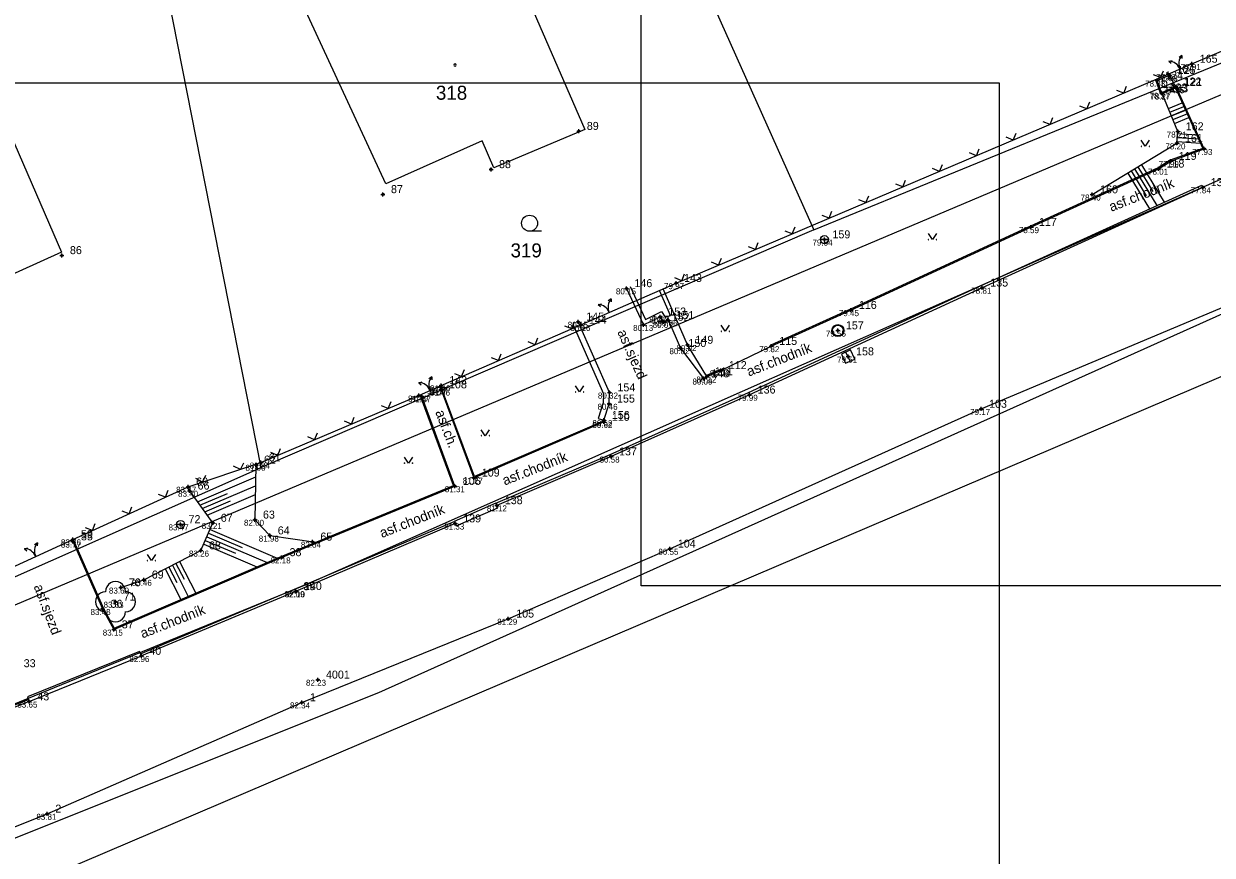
# Model space of a CAD drawing. Extents: x -454285 to -453563, y -1108687 to -1108249.
# Drawn here: x -454078.1 to -454018.7, y -1108543.4 to -1108501.8 of the extents above; entities that cross this region are included whole.
import ezdxf

# ---------------------------------------------------------------- set-up
doc = ezdxf.new("R2010")
doc.units = 0
for name, color, linetype in [('1', 7, 'Continuous'), ('14', 7, 'Continuous'), ('15', 7, 'Continuous'), ('2', 7, 'Continuous'), ('23', 7, 'Continuous'), ('25', 7, 'Continuous'), ('beton', 7, 'Continuous'), ('BODY_T1_2018', 7, 'Continuous'), ('CISLA_T1_2018', 7, 'Continuous'), ('obrubník', 7, 'Continuous'), ('okraj asf.komunikace', 7, 'Continuous'), ('oplocení', 7, 'Continuous'), ('rozhraní', 7, 'Continuous'), ('rámy', 7, 'Continuous'), ('sloup', 7, 'Continuous'), ('svahy', 7, 'Continuous'), ('svahy-hrana', 7, 'Continuous'), ('svahy-pata', 7, 'Continuous'), ('T', 7, 'Continuous'), ('uliční vpusť', 7, 'Continuous'), ('VYSKY_T1_2018', 7, 'Continuous'), ('zeleň', 7, 'Continuous'), ('šachtice', 7, 'Continuous')]:
    doc.layers.add(name, color=color, linetype=linetype)

# ---------------------------------------------------------------- blocks, each defined once
blk = doc.blocks.new('Z402')
for start, end in [(0, 180), (180, 0)]:
    blk.add_arc((0, 0), 0.15, start, end)
blk = doc.blocks.new('Z3040')
blk.add_line((1.5, 0), (0, 0))
blk.add_circle((0, 1), 1)
blk = doc.blocks.new('PLOT05')
for q in [(-0.265, 0.265), (0.265, 0.265)]:
    blk.add_line((0, 0), q)
blk = doc.blocks.new('BRANKA')
for p, q in [((-0.351, 0.589), (-0.179, 0.552)), ((-0.351, 0.589), (-0.284, 0.449)), ((0.361, 0.583), (0.188, 0.549)), ((0.361, 0.583), (0.291, 0.445))]:
    blk.add_line(p, q)
for centre, start, end in [((-0.618, 0.03), 357.17506, 64.46884), ((0.619, 0.02), 114.58945, 181.88322)]:
    blk.add_arc(centre, 0.619, start, end)
blk = doc.blocks.new('EL.SLOUP')
blk.add_line((0.4, 0), (-0.4, 0))
blk.add_line((0.4, 0), (-0.4, 0))
blk.add_lwpolyline([(0.4, 0), (-0.4, 0)])
blk.add_lwpolyline([(0.4, 0), (-0.4, 0)])
blk.add_circle((0, 0), 0.4)
blk.add_circle((0, 0), 0.4)
for start, end in [(270, 0), (270, 0), (180, 270), (180, 270)]:
    blk.add_arc((0, 0), 0.4, start, end)
blk = doc.blocks.new('šachtice_kruh_velká')
for radius in [0.5, 0.495, 0.495, 0.455, 0.455, 0.45]:
    blk.add_circle((0, 0), radius)
blk = doc.blocks.new('vpusť')
for p, q in [((0.25, 0.25), (-0.25, 0.25)), ((-0.25, 0.25), (-0.25, -0.25)), ((-0.25, 0), (0.25, 0)), ((0.25, -0.25), (0.25, 0.25)), ((-0.25, -0.25), (0.25, -0.25))]:
    blk.add_line(p, q)
blk = doc.blocks.new('strom')
blk.add_circle((0, 0), 0.1)
for centre, start, end in [((0, 1.02), 359.2723, 180.7277), ((-1.01, 0.01), 89.2723, 270.7277), ((1.01, 0.01), 269.2723, 90.7277), ((0, -1), 179.2723, 0.7277)]:
    blk.add_arc(centre, 0.998, start, end)
blk = doc.blocks.new('PARK')
for p, q in [((0, 0), (-1, 1.5)), ((1, 1.5), (0, 0))]:
    blk.add_line(p, q)
for centre, start, end in [((-1, 0), 0, 180), ((1, 0), 0, 180), ((1, 0), 180, 0), ((-1, 0), 180, 0)]:
    blk.add_arc(centre, 0.05, start, end)
blk = doc.blocks.new('POINT_DISPLAY')
for p, q in [((-0.1, 0), (0.1, 0)), ((0, -0.1), (0, 0.1))]:
    blk.add_line(p, q)
blk.add_circle((0, 0), 0.05)
blk = doc.blocks.new('t1_2018')
at = {"layer": 'BODY_T1_2018'}
for p in [(-454019.7, -1108503.81), (-454020.87, -1108504.33), (-454020.81, -1108504.37), (-454021.43, -1108504.64), (-454020.51, -1108504.95), (-454020.47, -1108504.98), (-454021.21, -1108505.25), (-454021.17, -1108505.29), (-454050.34, -1108507.17), (-454020.4, -1108507.19), (-454020.44, -1108507.78), (-454019.07, -1108508.06), (-454020.75, -1108508.67), (-454054.73, -1108509.08), (-454021.36, -1108509.05), (-454060.13, -1108510.33), (-454024.68, -1108510.34), (-454019.15, -1108509.98), (-454027.74, -1108511.97), (-454038.06, -1108512.59), (-454076.18, -1108513.38), (-454047.96, -1108515.03), (-454045.48, -1108514.77), (-454030.17, -1108515), (-454036.74, -1108516.12), (-454050.37, -1108516.7), (-454050.24, -1108516.86), (-454047.1, -1108516.86), (-454046.27, -1108516.45), (-454046.1, -1108516.71), (-454045.86, -1108516.63), (-454037.39, -1108517.14), (-454045.26, -1108518.02), (-454044.91, -1108517.86), (-454040.72, -1108517.92), (-454036.88, -1108518.44), (-454043.24, -1108519.13), (-454057.22, -1108519.88), (-454044.11, -1108519.54), (-454043.94, -1108519.44), (-454058.33, -1108520.39), (-454058.19, -1108520.43), (-454057.23, -1108520.09), (-454048.81, -1108520.24), (-454041.8, -1108520.35), (-454048.83, -1108520.8), (-454030.23, -1108521.06), (-454049.09, -1108521.62), (-454049.09, -1108521.71), (-454048.73, -1108523.44), (-454066.48, -1108523.85), (-454066.24, -1108523.74), (-454055.59, -1108524.5), (-454069.87, -1108524.95), (-454069.8, -1108525.15), (-454056.54, -1108524.92), (-454054.44, -1108525.88), (-454070.25, -1108526.83), (-454068.64, -1108526.76), (-454066.53, -1108526.6), (-454056.52, -1108526.79), (-454075.63, -1108527.58), (-454075.63, -1108527.69), (-454065.79, -1108527.39), (-454063.66, -1108527.7), (-454069.23, -1108528.14), (-454045.79, -1108528.05), (-454065.2, -1108528.48), (-454073.23, -1108529.99), (-454072.09, -1108529.6), (-454064.51, -1108530.18), (-454064.48, -1108530.17), (-454074.15, -1108531.06), (-454073.5, -1108530.7), (-454053.87, -1108531.55), (-454073.59, -1108532.09), (-454072.21, -1108533.41), (-454063.38, -1108534.6), (-454077.81, -1108535.69), (-454064.18, -1108535.73), (-454076.91, -1108541.3)]:
    blk.add_blockref('POINT_DISPLAY', p, dxfattribs=at)
at = {"layer": 'CISLA_T1_2018'}
for s, p in [('165', (-454019.3, -1108503.75)), ('124', (-454021.03, -1108504.58)), ('164', (-454020.47, -1108504.27)), ('125', (-454020.41, -1108504.31)), ('123', (-454020.81, -1108505.19)), ('163', (-454020.77, -1108505.23)), ('122', (-454020.11, -1108504.89)), ('121', (-454020.07, -1108504.92)), ('89', (-454049.94, -1108507.11)), ('162', (-454020, -1108507.13)), ('161', (-454020.04, -1108507.72)), ('118', (-454020.96, -1108508.99)), ('119', (-454020.35, -1108508.61)), ('88', (-454054.33, -1108509.02)), ('134', (-454018.75, -1108509.92)), ('87', (-454059.73, -1108510.27)), ('160', (-454024.28, -1108510.28)), ('117', (-454027.34, -1108511.91)), ('159', (-454037.66, -1108512.53)), ('86', (-454075.78, -1108513.32)), ('143', (-454045.08, -1108514.71)), ('135', (-454029.77, -1108514.94)), ('146', (-454047.56, -1108514.97)), ('116', (-454036.34, -1108516.06)), ('145', (-454049.97, -1108516.64)), ('153', (-454045.87, -1108516.39)), ('152', (-454045.7, -1108516.65)), ('151', (-454045.46, -1108516.57)), ('144', (-454049.84, -1108516.8)), ('147', (-454046.7, -1108516.8)), ('157', (-454036.99, -1108517.08)), ('149', (-454044.51, -1108517.8)), ('115', (-454040.32, -1108517.86)), ('150', (-454044.86, -1108517.96)), ('158', (-454036.48, -1108518.38)), ('112', (-454042.84, -1108519.07)), ('148', (-454043.71, -1108519.48)), ('111', (-454043.54, -1108519.38)), ('108', (-454056.83, -1108520.03)), ('142', (-454056.82, -1108519.82)), ('154', (-454048.41, -1108520.18)), ('136', (-454041.4, -1108520.29)), ('141', (-454057.93, -1108520.33)), ('107', (-454057.79, -1108520.37)), ('155', (-454048.43, -1108520.74)), ('103', (-454029.83, -1108521)), ('156', (-454048.69, -1108521.56)), ('110', (-454048.69, -1108521.65)), ('62', (-454066.08, -1108523.79)), ('61', (-454065.84, -1108523.68)), ('137', (-454048.33, -1108523.38)), ('109', (-454055.19, -1108524.44)), ('60', (-454069.47, -1108524.89)), ('106', (-454056.14, -1108524.86)), ('66', (-454069.4, -1108525.09)), ('138', (-454054.04, -1108525.82)), ('72', (-454069.85, -1108526.77)), ('67', (-454068.24, -1108526.7)), ('63', (-454066.13, -1108526.54)), ('139', (-454056.12, -1108526.73)), ('64', (-454065.39, -1108527.33)), ('35', (-454075.23, -1108527.63)), ('59', (-454075.23, -1108527.52)), ('65', (-454063.26, -1108527.64)), ('104', (-454045.39, -1108527.99)), ('68', (-454068.83, -1108528.08)), ('38', (-454064.8, -1108528.42)), ('69', (-454071.69, -1108529.54)), ('70', (-454072.83, -1108529.93)), ('39', (-454064.11, -1108530.12)), ('140', (-454064.08, -1108530.11)), ('71', (-454073.1, -1108530.64)), ('36', (-454073.75, -1108531)), ('105', (-454053.47, -1108531.49)), ('37', (-454073.19, -1108532.03)), ('40', (-454071.81, -1108533.35)), ('33', (-454078.09, -1108533.97)), ('4001', (-454062.98, -1108534.54)), ('43', (-454077.41, -1108535.63)), ('1', (-454063.78, -1108535.67)), ('2', (-454076.51, -1108541.24))]:
    blk.add_text(s, height=0.4, dxfattribs=at).set_placement(p)
at = {"layer": 'VYSKY_T1_2018'}
for s, p in [('77.91', (-454020.25, -1108504.11)), ('77.97', (-454021.47, -1108504.63)), ('77.93', (-454021.41, -1108504.67)), ('78.33', (-454022.03, -1108504.94)), ('77.95', (-454021.11, -1108505.25)), ('77.95', (-454021.07, -1108505.28)), ('78.27', (-454021.81, -1108505.55)), ('78.27', (-454021.77, -1108505.59)), ('78.21', (-454020.95, -1108507.49)), ('78.20', (-454021.015, -1108508.08)), ('77.93', (-454019.67, -1108508.36)), ('78.01', (-454021.885, -1108509.35)), ('77.99', (-454021.35, -1108508.97)), ('78.40', (-454025.255, -1108510.64)), ('77.84', (-454019.75, -1108510.28)), ('78.59', (-454028.34, -1108512.27)), ('79.54', (-454038.66, -1108512.89)), ('80.15', (-454048.485, -1108515.33)), ('79.97', (-454046.08, -1108515.07)), ('78.81', (-454030.72, -1108515.3)), ('79.45', (-454037.34, -1108516.42)), ('80.15', (-454050.895, -1108517)), ('80.16', (-454050.765, -1108517.16)), ('80.13', (-454047.625, -1108517.16)), ('80.08', (-454046.82, -1108516.75)), ('80.07', (-454046.65, -1108517.01)), ('80.06', (-454046.41, -1108516.93)), ('79.55', (-454037.99, -1108517.44)), ('80.02', (-454045.81, -1108518.32)), ('80.02', (-454045.46, -1108518.16)), ('79.82', (-454041.32, -1108518.22)), ('79.51', (-454037.43, -1108518.74)), ('80.02', (-454043.79, -1108519.43)), ('81.46', (-454057.77, -1108520.18)), ('80.09', (-454044.66, -1108519.84)), ('80.12', (-454044.465, -1108519.74)), ('81.49', (-454058.88, -1108520.69)), ('81.47', (-454058.74, -1108520.73)), ('81.46', (-454057.78, -1108520.39)), ('80.32', (-454049.385, -1108520.54)), ('79.99', (-454042.4, -1108520.65)), ('80.46', (-454049.405, -1108521.1)), ('79.17', (-454030.78, -1108521.36)), ('80.62', (-454049.665, -1108521.92)), ('80.62', (-454049.665, -1108522.01)), ('80.58', (-454049.305, -1108523.74)), ('81.90', (-454067.005, -1108524.15)), ('81.84', (-454066.79, -1108524.04)), ('81.27', (-454056.14, -1108524.8)), ('83.47', (-454070.47, -1108525.25)), ('83.40', (-454070.375, -1108525.45)), ('81.31', (-454057.04, -1108525.22)), ('81.12', (-454054.94, -1108526.18)), ('83.47', (-454070.85, -1108527.13)), ('83.21', (-454069.19, -1108527.06)), ('82.00', (-454067.08, -1108526.9)), ('81.33', (-454057.07, -1108527.09)), ('83.76', (-454076.23, -1108527.88)), ('81.98', (-454066.34, -1108527.69)), ('83.77', (-454076.23, -1108527.99)), ('83.26', (-454069.83, -1108528.44)), ('82.04', (-454064.235, -1108528)), ('80.55', (-454046.365, -1108528.35)), ('82.18', (-454065.75, -1108528.78)), ('83.69', (-454073.83, -1108530.29)), ('83.46', (-454072.69, -1108529.9)), ('82.09', (-454065.055, -1108530.47)), ('82.10', (-454065.035, -1108530.48)), ('83.48', (-454074.75, -1108531.36)), ('83.63', (-454074.1, -1108531)), ('81.29', (-454054.42, -1108531.85)), ('83.15', (-454074.14, -1108532.39)), ('82.96', (-454072.81, -1108533.71)), ('82.23', (-454063.98, -1108534.9)), ('83.65', (-454078.41, -1108535.99)), ('82.34', (-454064.78, -1108536.03)), ('83.81', (-454077.46, -1108541.6))]:
    blk.add_text(s, height=0.3, dxfattribs=at).set_placement(p)

msp = doc.modelspace()

# ---------------------------------------------------------------- linework, layer by layer
at = {"layer": '1'}
for p, q in [((-454052.497, -1108481.021), (-454038.597, -1108512.101)), ((-453969.347, -1108484.681), (-454124.757, -1108550.421)), ((-454066.217, -1108523.991), (-454072.057, -1108494.361)), ((-454054.507, -1108496.801), (-454050.047, -1108507.081)), ((-454059.987, -1108509.811), (-454064.107, -1108500.931)), ((-454038.597, -1108512.101), (-454015.197, -1108502.531)), ((-453988.627, -1108506.811), (-454099.187, -1108553.971)), ((-454078.747, -1108507.331), (-454076.207, -1108513.221)), ((-454050.047, -1108507.081), (-454054.597, -1108509.001)), ((-454055.167, -1108507.651), (-454059.987, -1108509.811)), ((-454054.597, -1108509.001), (-454055.167, -1108507.651)), ((-454038.597, -1108512.101), (-454066.217, -1108523.991)), ((-454076.207, -1108513.221), (-454081.447, -1108515.581)), ((-454091.257, -1108535.081), (-454066.217, -1108523.991))]:
    msp.add_line(p, q, dxfattribs=at)
at = {"layer": '2'}
for p, q in [((-454063.887, -1108529.801), (-453990.237, -1108497.151)), ((-453993.337, -1108505.161), (-454060.357, -1108535.251)), ((-454114.597, -1108550.531), (-454063.887, -1108529.801)), ((-454060.357, -1108535.251), (-454108.957, -1108554.681))]:
    msp.add_line(p, q, dxfattribs=at)
at = {"layer": 'beton'}
msp.add_lwpolyline([(-454020.51, -1108504.95), (-454021.21, -1108505.25), (-454021.43, -1108504.64), (-454020.81, -1108504.37)], close=True, dxfattribs=at)
for points in [[(-454020.51, -1108504.95), (-454020.489, -1108504.998), (-454021.241, -1108505.32), (-454021.496, -1108504.612)], [(-454047.96, -1108515.03), (-454047.1, -1108516.86), (-454046.27, -1108516.45), (-454046.1, -1108516.71), (-454045.86, -1108516.63), (-454045.26, -1108518.02), (-454044.11, -1108519.54), (-454043.94, -1108519.44), (-454044.91, -1108517.86), (-454046.122, -1108515.052)], [(-454047.779, -1108514.945), (-454047.006, -1108516.59), (-454046.2, -1108516.192), (-454046.017, -1108516.472), (-454045.764, -1108516.387), (-454046.306, -1108515.131)], [(-454050.645, -1108516.821), (-454049.112, -1108520.298), (-454049.128, -1108520.748), (-454049.376, -1108521.529), (-454049.09, -1108521.62), (-454048.83, -1108520.8), (-454048.81, -1108520.24), (-454050.37, -1108516.7)]]:
    msp.add_lwpolyline(points, dxfattribs=at)
at = {"layer": 'obrubník'}
for points in [[(-454020.512, -1108505.008), (-454019.138, -1108508.031), (-454020.772, -1108508.625), (-454021.384, -1108509.006), (-454027.761, -1108511.925), (-454036.761, -1108516.075), (-454040.741, -1108517.875), (-454040.72, -1108517.92), (-454036.74, -1108516.12), (-454027.74, -1108511.97), (-454021.36, -1108509.05), (-454020.75, -1108508.67), (-454019.07, -1108508.06), (-454020.467, -1108504.987), (-454020.512, -1108505.008)], [(-454019.2, -1108509.871), (-454019.15, -1108509.98), (-454030.17, -1108515), (-454041.8, -1108520.35), (-454048.73, -1108523.44), (-454054.44, -1108525.88), (-454054.488, -1108525.77), (-454048.778, -1108523.33), (-454041.85, -1108520.241), (-454030.22, -1108514.891)], [(-454054.488, -1108525.77), (-454056.567, -1108526.68), (-454056.467, -1108526.909), (-454054.387, -1108525.999)], [(-454056.567, -1108526.68), (-454056.52, -1108526.79), (-454064.51, -1108530.18), (-454072.21, -1108533.41), (-454072.256, -1108533.299), (-454064.557, -1108530.069)], [(-454072.304, -1108533.178), (-454077.904, -1108535.458), (-454077.81, -1108535.69), (-454072.21, -1108533.41)], [(-454077.81, -1108535.69), (-454086.77, -1108539.21), (-454095.67, -1108542.66), (-454095.713, -1108542.548), (-454086.814, -1108539.098), (-454077.855, -1108535.579)]]:
    msp.add_lwpolyline(points, close=True, dxfattribs=at)
for points in [[(-454043.94, -1108519.44), (-454043.24, -1108519.13), (-454043.261, -1108519.085), (-454043.96, -1108519.394), (-454043.94, -1108519.44)], [(-454075.67, -1108527.598), (-454074.15, -1108531.06), (-454073.59, -1108532.09), (-454065.2, -1108528.48), (-454056.54, -1108524.92), (-454058.223, -1108520.341)], [(-454075.625, -1108527.578), (-454074.105, -1108531.038), (-454073.568, -1108532.026), (-454065.219, -1108528.434), (-454056.604, -1108524.892), (-454058.268, -1108520.362)], [(-454057.295, -1108519.915), (-454055.59, -1108524.5), (-454049.09, -1108521.71), (-454049.11, -1108521.664), (-454055.561, -1108524.433), (-454057.25, -1108519.894)]]:
    msp.add_lwpolyline(points, dxfattribs=at)
at = {"layer": 'okraj asf.komunikace'}
msp.add_lwpolyline([(-454112.32, -1108555.84), (-454100.65, -1108550.87), (-454089.58, -1108546.38), (-454076.91, -1108541.3), (-454064.18, -1108535.73), (-454053.87, -1108531.55), (-454045.79, -1108528.05), (-454030.23, -1108521.06), (-454017.66, -1108515.77), (-454004.84, -1108509.89), (-453993.47, -1108504.93), (-453991.99, -1108504.49), (-453990.15, -1108504.23), (-453988.99, -1108504.84), (-453987.94, -1108505.97), (-453986.82, -1108510.84)], dxfattribs=at)
at = {"layer": 'oplocení'}
msp.add_lwpolyline([(-454125.24, -1108545.86), (-454124.84, -1108549.82), (-454113.81, -1108544.95), (-454112.8, -1108544.5), (-454100.47, -1108538.97), (-454097.57, -1108537.59), (-454092.06, -1108535.05), (-454080.32, -1108529.69), (-454079.35, -1108529.29), (-454075.63, -1108527.58), (-454069.87, -1108524.95), (-454066.24, -1108523.74), (-454058.33, -1108520.39), (-454057.22, -1108519.88), (-454050.24, -1108516.86), (-454045.48, -1108514.77), (-454020.87, -1108504.33), (-454019.7, -1108503.81), (-454015.75, -1108502.12)], dxfattribs=at)
at = {"layer": 'rozhraní'}
msp.add_lwpolyline([(-454043.24, -1108519.13), (-454040.72, -1108517.92)], dxfattribs=at)
at = {"layer": 'rámy'}
for points in [[(-454047.225, -1108469.854), (-453948.057, -1108469.854), (-453948.057, -1108529.906), (-454047.225, -1108529.906)], [(-454128.499, -1108504.754), (-454029.331, -1108504.754), (-454029.331, -1108564.805), (-454128.499, -1108564.805)]]:
    msp.add_lwpolyline(points, close=True, dxfattribs=at)
at = {"layer": 'svahy'}
for p, q in [((-454020.866, -1108506.04), (-454020.171, -1108505.758)), ((-454020.791, -1108506.225), (-454020.088, -1108505.94)), ((-454020.716, -1108506.41), (-454020.006, -1108506.122)), ((-454020.641, -1108506.596), (-454019.923, -1108506.305)), ((-454020.566, -1108506.781), (-454019.84, -1108506.487)), ((-454020.406, -1108507.285), (-454019.447, -1108507.35)), ((-454020.434, -1108507.685), (-454019.259, -1108507.764)), ((-454020.42, -1108507.485), (-454019.353, -1108507.557)), ((-454022.731, -1108509.163), (-454021.985, -1108510.399)), ((-454022.56, -1108509.06), (-454021.451, -1108510.896)), ((-454022.389, -1108508.957), (-454021.643, -1108510.192)), ((-454022.218, -1108508.853), (-454021.085, -1108510.729)), ((-454022.902, -1108509.267), (-454021.818, -1108511.063)), ((-454069.403, -1108525.701), (-454066.491, -1108524.46)), ((-454069.163, -1108526.034), (-454066.499, -1108524.899)), ((-454069.283, -1108525.868), (-454067.909, -1108525.282)), ((-454069.043, -1108526.2), (-454067.753, -1108525.65)), ((-454068.923, -1108526.367), (-454066.507, -1108525.337)), ((-454068.935, -1108527.45), (-454065.924, -1108528.737)), ((-454068.856, -1108527.266), (-454067.176, -1108527.984)), ((-454068.778, -1108527.082), (-454065.417, -1108528.519)), ((-454069.092, -1108527.818), (-454066.431, -1108528.955)), ((-454069.014, -1108527.634), (-454067.508, -1108528.277)), ((-454070.482, -1108528.779), (-454070.077, -1108529.572)), ((-454070.304, -1108528.688), (-454069.494, -1108530.273)), ((-454071.016, -1108529.052), (-454070.231, -1108530.59)), ((-454070.838, -1108528.961), (-454070.439, -1108529.742)), ((-454070.66, -1108528.87), (-454069.863, -1108530.432))]:
    msp.add_line(p, q, dxfattribs=at)
at = {"layer": 'svahy-hrana'}
for points in [[(-454024.68, -1108510.34), (-454020.44, -1108507.78), (-454020.4, -1108507.19), (-454021.17, -1108505.29)], [(-454073.23, -1108529.99), (-454072.09, -1108529.6), (-454069.23, -1108528.14), (-454068.64, -1108526.76), (-454069.926, -1108524.975)]]:
    msp.add_lwpolyline(points, dxfattribs=at)
at = {"layer": 'svahy-pata'}
msp.add_lwpolyline([(-454066.48, -1108523.85), (-454066.53, -1108526.6), (-454065.79, -1108527.39), (-454063.493, -1108527.724)], dxfattribs=at)

# ---------------------------------------------------------------- block references
msp.add_blockref('t1_2018', (0, 0))
at = {"layer": '23', "xscale": 0.4, "yscale": 0.4000000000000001}
msp.add_blockref('Z3040', (-454052.803, -1108512.174), dxfattribs=at)
at = {"layer": '25', "xscale": 0.4, "yscale": 0.4000000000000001}
msp.add_blockref('Z402', (-454056.525, -1108503.867), dxfattribs=at)
at = {"layer": 'oplocení'}
for name, p, rotation in [('BRANKA', (-454020.285, -1108504.07), 23.962488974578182), ('PLOT05', (-454021.26, -1108504.495), 22.987521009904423), ('PLOT05', (-454023.101, -1108505.276), 22.987521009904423), ('PLOT05', (-454024.942, -1108506.057), 22.987521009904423), ('PLOT05', (-454026.783, -1108506.838), 22.987521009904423), ('PLOT05', (-454028.624, -1108507.62), 22.987521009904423), ('PLOT05', (-454030.466, -1108508.401), 22.987521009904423), ('PLOT05', (-454032.307, -1108509.182), 22.987521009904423), ('PLOT05', (-454034.148, -1108509.963), 22.987521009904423), ('PLOT05', (-454035.989, -1108510.744), 22.987521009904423), ('PLOT05', (-454037.83, -1108511.525), 22.987521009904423), ('PLOT05', (-454039.671, -1108512.306), 22.987521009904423), ('PLOT05', (-454041.513, -1108513.087), 22.987521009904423), ('PLOT05', (-454043.354, -1108513.868), 22.987521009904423), ('PLOT05', (-454045.195, -1108514.649), 22.987521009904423), ('BRANKA', (-454048.818, -1108516.236), 23.70510731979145), ('PLOT05', (-454050.691, -1108517.055), 23.39643426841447), ('PLOT05', (-454052.527, -1108517.849), 23.39643426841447), ('PLOT05', (-454054.362, -1108518.644), 23.39643426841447), ('PLOT05', (-454056.198, -1108519.438), 23.39643426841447), ('BRANKA', (-454057.775, -1108520.135), 24.676863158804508), ('PLOT05', (-454059.863, -1108521.039), 22.95336397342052), ('PLOT05', (-454061.705, -1108521.819), 22.95336397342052), ('PLOT05', (-454063.546, -1108522.599), 22.95336397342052), ('PLOT05', (-454065.388, -1108523.379), 22.95336397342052), ('PLOT05', (-454067.26, -1108524.08), 18.434948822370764), ('PLOT05', (-454069.157, -1108524.712), 18.434948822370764), ('PLOT05', (-454071.006, -1108525.469), 24.54130733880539), ('PLOT05', (-454072.825, -1108526.299), 24.54130733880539), ('PLOT05', (-454074.644, -1108527.13), 24.54130733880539), ('BRANKA', (-454077.49, -1108528.435), 24.687173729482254)]:
    msp.add_blockref(name, p, dxfattribs=dict(at, rotation=rotation))
at = {"layer": 'sloup', "xscale": 0.5, "yscale": 0.5}
for p in [(-454038.06, -1108512.59), (-454070.25, -1108526.83)]:
    msp.add_blockref('EL.SLOUP', p, dxfattribs=at)
at = {"layer": 'uliční vpusť', "rotation": 114.70324345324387}
msp.add_blockref('vpusť', (-454036.88, -1108518.44), dxfattribs=at)
at = {"layer": 'zeleň'}
for name, p, xscale, yscale in [('PARK', (-454022.023, -1108507.929), 0.2, 0.20000000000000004), ('PARK', (-454032.663, -1108512.592), 0.2, 0.20000000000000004), ('PARK', (-454043.022, -1108517.172), 0.2, 0.20000000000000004), ('PARK', (-454050.299, -1108520.209), 0.2, 0.20000000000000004), ('PARK', (-454055.015, -1108522.401), 0.2, 0.20000000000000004), ('PARK', (-454058.854, -1108523.771), 0.2, 0.20000000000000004), ('PARK', (-454071.709, -1108528.638), 0.2, 0.20000000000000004), ('strom', (-454073.5, -1108530.7), 0.5, 0.5)]:
    msp.add_blockref(name, p, dxfattribs=dict(at, xscale=xscale, yscale=yscale))
at = {"layer": 'šachtice', "xscale": 0.6, "yscale": 0.6}
msp.add_blockref('šachtice_kruh_velká', (-454037.39, -1108517.14), dxfattribs=at)

# ---------------------------------------------------------------- texts
at = {"layer": '14'}
msp.add_text('319', height=0.7, dxfattribs=at).set_placement((-454053.752, -1108513.482))
at = {"layer": '15'}
msp.add_text('318', height=0.7, dxfattribs=at).set_placement((-454057.483, -1108505.601))
at = {"layer": 'T'}
msp.add_text('b.', height=0.5, dxfattribs=at).set_placement((-454021.256, -1108505.017))
for s, rotation, p in [('asf.chodník', 21.48249, (-454023.719, -1108511.207)), ('asf.sjezd', 293.78203, (-454048.427, -1108517.215)), ('asf.chodník', 21.48249, (-454041.834, -1108519.443)), ('asf.ch.', 290.78825, (-454057.525, -1108521.215)), ('asf.chodník', 21.48249, (-454054.042, -1108524.892)), ('asf.chodník', 21.48249, (-454060.181, -1108527.514)), ('asf.sjezd', 290.78825, (-454077.603, -1108529.933)), ('asf.chodník', 21.48249, (-454072.148, -1108532.536))]:
    msp.add_text(s, height=0.5, rotation=rotation, dxfattribs=at).set_placement(p)

doc.saveas('drawing.dxf')
